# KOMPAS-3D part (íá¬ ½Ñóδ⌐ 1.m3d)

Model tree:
1. Эскиз:1
2. Операция выдавливания:1
     Расстояние 1 = 11
3. Эскиз:2
4. Вырезать элемент выдавливания:1
     Расстояние 1 = 34.8
5. Скругление:1
     Радиус = 1
6. Скругление:2
     Радиус = 2
7. Эскиз:3
8. Вырезать элемент выдавливания:2
     Расстояние 1 = 0.2
9. Скругление:5
     Радиус = 0.2
10. Скругление:6
     Радиус = 0.2
11. Эскиз:6
12. Операция выдавливания:3
     Расстояние 1 = 2
13. Скругление:8
     Радиус = 0.5
14. Эскиз:7
15. Вырезать элемент выдавливания:4
     Расстояние 1 = 0.2
16. Скругление:9
     Радиус = 0.5
17. Эскиз:8
18. Операция выдавливания:4
     Расстояние 1 = 0.1

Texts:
  бак левый 1
  Сплав АЛ8  ГОСТ 1583-93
